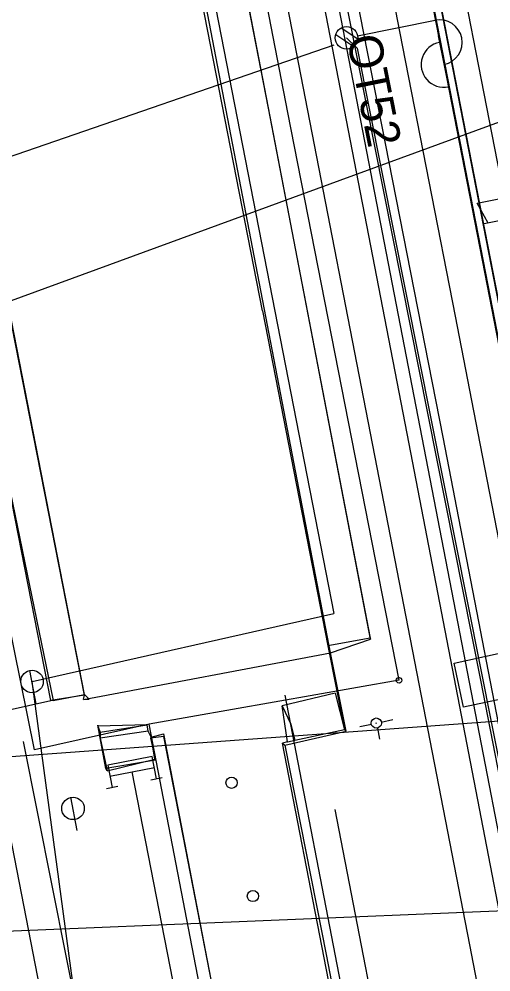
# Model space of a CAD drawing. Extents: x -545736 to -544888, y -1122892 to -1119128.
# Drawn here: x -545210.15 to -545189.26, y -1122030.09 to -1121987.93 of the extents above; entities that cross this region are included whole.
import ezdxf

# ---------------------------------------------------------------- set-up
doc = ezdxf.new("R2010")
doc.units = 0
for name, color, linetype in [('osvětlené plochy-hodnota-obrys', 7, 'Continuous'), ('Podbarveni_Nastupiste', 7, 'Continuous'), ('Podbarveni_Zastreseni_Pozemni', 7, 'Continuous'), ('Vrstva 1', 7, 'Continuous'), ('Vrstva 1 - Koleje', 7, 'Continuous'), ('Vrstva 12', 7, 'Continuous'), ('Vrstva 14_zastreseni a nastupiste', 7, 'Continuous'), ('Vrstva 15', 7, 'Continuous'), ('Vrstva 16_plochy', 7, 'Continuous'), ('Vrstva 17', 7, 'Continuous'), ('Vrstva 23', 7, 'Continuous'), ('Vrstva 25', 7, 'Continuous'), ('Vrstva 26', 7, 'Continuous'), ('Vrstva 33 - prvky sdelzar', 7, 'Continuous'), ('Vrstva 36', 7, 'Continuous'), ('Vrstva 4 - Teren - stezky - prechody - plochy', 7, 'Continuous'), ('Vrstva 41', 7, 'Continuous'), ('Vrstva 42', 7, 'Continuous'), ('Vrstva 43', 7, 'Continuous'), ('Vrstva 44', 7, 'Continuous'), ('Vrstva 51', 7, 'Continuous'), ('Vrstva 63', 7, 'Continuous')]:
    doc.layers.add(name, color=color, linetype=linetype)

msp = doc.modelspace()

# ---------------------------------------------------------------- linework, layer by layer
at = {"layer": 'osvětlené plochy-hodnota-obrys'}
for points in [[(-545132.033, -1122317.745), (-545201.844, -1121957.194), (-545188.779, -1121954.655), (-545199.189, -1121901.389)], [(-545201.844, -1121957.194), (-545207.148, -1121958.23), (-545196.216, -1122014.238)], [(-545179.449, -1122198.287), (-545199.55, -1122091.48), (-545209.58, -1122017.245), (-545196.216, -1122014.238)]]:
    msp.add_lwpolyline(points, dxfattribs=at)
at = {"layer": 'Podbarveni_Nastupiste'}
msp.add_lwpolyline([(-545198.773, -1121951.627), (-545191.691, -1121987.986), (-545182.222, -1122036.609), (-545172.438, -1122086.699), (-545162.999, -1122135.094), (-545153.274, -1122184.937), (-545142.505, -1122240.181), (-545142.306, -1122241.006)], dxfattribs=at)
at = {"layer": 'Podbarveni_Zastreseni_Pozemni'}
msp.add_lwpolyline([(-545197.881, -1121954.495), (-545191.312, -1121988.174), (-545181.806, -1122036.914), (-545172.146, -1122086.438), (-545162.65, -1122135.125), (-545152.971, -1122184.749), (-545143.515, -1122233.227)], dxfattribs=at)
at = {"layer": 'Vrstva 1'}
msp.add_line((-545199.187, -1122051.823), (-545205.146, -1122021.242), dxfattribs=at)
for points in [[(-545171.524, -1122125.069), (-545174.635, -1122109.111), (-545178.563, -1122088.801), (-545181.831, -1122072.035), (-545185.39, -1122053.802), (-545190.2, -1122028.892), (-545193.908, -1122009.819), (-545198.17, -1121987.873), (-545202.45, -1121965.839), (-545203.994, -1121957.813)], [(-545176.125, -1122125.966), (-545177.056, -1122121.203), (-545182.157, -1122094.956), (-545185.515, -1122077.639), (-545188.604, -1122061.78), (-545193.373, -1122037.292), (-545196.156, -1122022.904)]]:
    msp.add_lwpolyline(points, dxfattribs=at)
at = {"layer": 'Vrstva 1 - Koleje'}
msp.add_lwpolyline([(-545199.342, -1121957.379), (-545196.999, -1121969.551), (-545195.085, -1121979.364), (-545193.173, -1121989.165), (-545190.849, -1122001.079), (-545189.753, -1122006.71), (-545187.83, -1122016.562), (-545185.924, -1122026.325), (-545184.013, -1122036.136), (-545182.107, -1122045.899), (-545180.267, -1122055.344), (-545178.296, -1122065.456), (-545176.383, -1122075.263), (-545174.481, -1122085.012)], dxfattribs=at)
at = {"layer": 'Vrstva 12'}
for p, q in [((-545194.605, -1122015.329), (-545194.591, -1122015.372)), ((-545196.48, -1122015.667), (-545196.366, -1122015.979)), ((-545207.256, -1122017.843), (-545208.742, -1122018.083)), ((-545208.65, -1122018.084), (-545207.25, -1122017.815)), ((-545207.25, -1122017.815), (-545207.256, -1122017.843)), ((-545196.154, -1122017.763), (-545198.512, -1122018.313)), ((-545196.154, -1122017.763), (-545195.739, -1122019.386)), ((-545208.65, -1122018.084), (-545208.742, -1122018.083)), ((-545206.57, -1122019.479), (-545204.476, -1122019.159)), ((-545204.438, -1122019.437), (-545206.567, -1122019.748)), ((-545203.763, -1122019.561), (-545203.751, -1122019.67)), ((-545195.668, -1122019.443), (-545195.739, -1122019.386)), ((-545204.299, -1122019.698), (-545204.329, -1122019.745)), ((-545204.143, -1122020.682), (-545204.112, -1122020.72)), ((-545206.251, -1122021.196), (-545206.312, -1122021.094))]:
    msp.add_line(p, q, dxfattribs=at)
for points in [[(-545221.457, -1121952.473), (-545217.829, -1121971.245), (-545212.72, -1121997.564), (-545210.75, -1122007.836), (-545208.65, -1122018.084)], [(-545198.393, -1122020.062), (-545195.668, -1122019.443), (-545196.366, -1122015.979), (-545194.591, -1122015.372), (-545199.107, -1121991.861), (-545202.9, -1121972.236), (-545205.869, -1121956.965), (-545205.949, -1121957.005), (-545202.951, -1121972.246), (-545199.128, -1121991.88), (-545194.605, -1122015.329), (-545196.48, -1122015.667), (-545195.739, -1122019.386), (-545197.952, -1122019.845), (-545198.251, -1122019.924), (-545198.272, -1122019.909), (-545198.489, -1122019.971)], [(-545198.272, -1122019.909), (-545198.512, -1122018.313), (-545198.121, -1122019.129), (-545198.121, -1122019.129), (-545197.952, -1122019.845)], [(-545206.672, -1122019.216), (-545206.57, -1122019.479), (-545206.567, -1122019.748), (-545206.251, -1122021.196), (-545204.143, -1122020.682), (-545204.299, -1122019.698), (-545204.438, -1122019.437), (-545204.476, -1122019.159), (-545206.672, -1122019.216)], [(-545204.299, -1122019.698), (-545203.763, -1122019.561), (-545196.412, -1122057.677), (-545191.231, -1122084.009), (-545184.671, -1122117.574), (-545184.668, -1122117.607), (-545191.105, -1122084.578), (-545196.358, -1122057.64), (-545203.751, -1122019.67), (-545204.329, -1122019.745), (-545204.112, -1122020.72), (-545206.312, -1122021.094), (-545206.672, -1122019.168), (-545206.672, -1122019.216)], [(-545206.558, -1122019.477), (-545206.57, -1122019.479)], [(-545179.655, -1122116.54), (-545186.14, -1122083.56), (-545191.388, -1122056.521), (-545196.648, -1122029.468), (-545198.489, -1122019.971), (-545198.393, -1122020.062), (-545196.548, -1122029.388), (-545191.323, -1122056.562), (-545186.056, -1122083.545), (-545179.629, -1122116.564)]]:
    msp.add_lwpolyline(points, dxfattribs=at)
at = {"layer": 'Vrstva 14_zastreseni a nastupiste'}
for points in [[(-545198.773, -1121951.627), (-545198.793, -1121951.631), (-545197.668, -1121957.434), (-545195.753, -1121967.224), (-545195.374, -1121969.187), (-545193.463, -1121979.015), (-545191.56, -1121988.764), (-545189.639, -1121998.596), (-545187.731, -1122008.385), (-545185.791, -1122018.31), (-545183.91, -1122027.957), (-545182.003, -1122037.734), (-545180.094, -1122047.536), (-545178.189, -1122057.285), (-545176.275, -1122067.11), (-545174.372, -1122076.877), (-545172.469, -1122086.648)], [(-545198.773, -1121951.627), (-545197.637, -1121957.485), (-545195.722, -1121967.275), (-545195.343, -1121969.238), (-545193.432, -1121979.066), (-545191.529, -1121988.815), (-545189.608, -1121998.647), (-545187.7, -1122008.436), (-545185.76, -1122018.361), (-545183.879, -1122028.008), (-545181.972, -1122037.785), (-545180.063, -1122047.587), (-545178.158, -1122057.336), (-545176.244, -1122067.161), (-545174.341, -1122076.928), (-545172.438, -1122086.699)], [(-545143.529, -1122233.23), (-545153.022, -1122184.547), (-545162.697, -1122134.935), (-545172.201, -1122086.2), (-545181.882, -1122036.553), (-545191.387, -1121987.814), (-545197.884, -1121954.495)], [(-545197.881, -1121954.495), (-545191.312, -1121988.174), (-545181.806, -1122036.914), (-545172.146, -1122086.438), (-545162.65, -1122135.125), (-545152.971, -1122184.749), (-545143.515, -1122233.229)]]:
    msp.add_lwpolyline(points, dxfattribs=at)
at = {"layer": 'Vrstva 15'}
for p, q in [((-545206.128, -1122021.433), (-545204.164, -1122021.051)), ((-545204.314, -1122021.589), (-545203.823, -1122021.494)), ((-545206.277, -1122021.972), (-545205.787, -1122021.876))]:
    msp.add_line(p, q, dxfattribs=at)
msp.add_lwpolyline([(-545204.069, -1122021.542), (-545204.26, -1122020.56), (-545206.223, -1122020.942), (-545206.032, -1122021.924)], dxfattribs=at)
at = {"layer": 'Vrstva 16_plochy'}
msp.add_lwpolyline([(-545172.438, -1122086.699), (-545174.341, -1122076.928), (-545176.244, -1122067.161), (-545178.158, -1122057.336), (-545180.063, -1122047.587), (-545181.972, -1122037.785), (-545183.879, -1122028.008), (-545185.76, -1122018.361), (-545187.7, -1122008.436), (-545189.608, -1121998.647), (-545191.529, -1121988.815), (-545193.432, -1121979.066), (-545195.343, -1121969.238), (-545195.722, -1121967.275), (-545197.637, -1121957.485), (-545198.773, -1121951.627)], dxfattribs=at)
at = {"layer": 'Vrstva 17'}
msp.add_lwpolyline([(-545209.978, -1122019.893), (-545196.019, -1122089.973), (-545200.414, -1122090.871), (-545193.769, -1122123.214)], dxfattribs=at)
at = {"layer": 'Vrstva 23'}
for p, q in [((-545196.366, -1122015.979), (-545209.259, -1121948.92)), ((-545207.256, -1122017.843), (-545220.407, -1121951.064)), ((-545207.25, -1122017.815), (-545220.159, -1121952.227)), ((-545199.383, -1122000.837), (-545196.48, -1122015.667)), ((-545207.294, -1122018.041), (-545207.256, -1122017.843)), ((-545207.053, -1122018.03), (-545207.25, -1122017.815)), ((-545179.479, -1122115.355), (-545198.377, -1122017.846)), ((-545207.294, -1122018.041), (-545207.053, -1122018.03)), ((-545185.499, -1122116.633), (-545204.397, -1122019.124))]:
    msp.add_line(p, q, dxfattribs=at)
for points in [[(-545199.383, -1122000.837), (-545202.829, -1121983.168), (-545208.015, -1121956.626), (-545209.317, -1121949.263), (-545209.259, -1121948.92), (-545210.612, -1121942.089), (-545208.554, -1121941.671), (-545213.053, -1121919.523), (-545225.888, -1121922.128)], [(-545209.473, -1122020.261), (-545214.34, -1121996.237), (-545218.36, -1121975.647), (-545223.024, -1121951.493), (-545220.12, -1121951.013)], [(-545193.331, -1122017.189), (-545198.252, -1121992.071), (-545203.434, -1121965.339)], [(-545207.294, -1122018.041), (-545196.366, -1122015.979)], [(-545193.331, -1122017.189), (-545204.397, -1122019.124), (-545209.473, -1122020.261)]]:
    msp.add_lwpolyline(points, dxfattribs=at)
msp.add_circle((-545193.331, -1122017.189), 0.125, dxfattribs=at)
at = {"layer": 'Vrstva 25'}
for p, q in [((-545195.164, -1121988.669), (-545191.731, -1121987.986)), ((-545195.89, -1121988.327), (-545195.159, -1121988.815)), ((-545196.129, -1121988.618), (-545195.333, -1121989.15)), ((-545191.594, -1121988.673), (-545191.087, -1121991.223))]:
    msp.add_line(p, q, dxfattribs=at)
msp.add_circle((-545195.654, -1121988.767), 0.5, dxfattribs=at)
msp.add_circle((-545195.654, -1121988.767), 0.5, dxfattribs=at)
for centre, start, end in [((-545191.536, -1121988.967), 281.2532, 101.2532), ((-545191.353, -1121989.95), 100.5506, 281.9557)]:
    msp.add_arc(centre, 1, start, end, dxfattribs=at)
at = {"layer": 'Vrstva 26'}
msp.add_lwpolyline([(-545195.654, -1121988.767), (-545195.18, -1121989.223), (-545187.569, -1122027.475), (-545180.363, -1122064.26), (-545172.911, -1122102.258), (-545175.755, -1122102.852), (-545177.675, -1122103.151), (-545178.018, -1122103.363), (-545177.842, -1122104.444), (-545175.244, -1122116.91), (-545174.048, -1122121.099), (-545173.902, -1122123.794), (-545172.196, -1122133.711), (-545171.232, -1122138.713), (-545170.128, -1122141.107), (-545170.035, -1122141.928), (-545170.255, -1122143.199), (-545168.934, -1122149.868), (-545168.557, -1122151.414), (-545168.549, -1122152.817), (-545167.193, -1122160.014), (-545166.201, -1122166.567)], dxfattribs=at)
at = {"layer": 'Vrstva 33 - prvky sdelzar'}
msp.add_line((-545187.81, -1121996.65), (-545189.569, -1121996.994), dxfattribs=at)
msp.add_lwpolyline([(-545189.38, -1121996.957), (-545189.879, -1121996.076), (-545188.622, -1121995.831), (-545188.752, -1121996.834)], dxfattribs=at)
at = {"layer": 'Vrstva 36'}
for centre in [(-545200.745, -1122021.718), (-545199.8, -1122026.732)]:
    msp.add_circle(centre, 0.25, dxfattribs=at)
at = {"layer": 'Vrstva 4 - Teren - stezky - prechody - plochy'}
for points in [[(-545202.565, -1121956.903), (-545201.056, -1121956.644), (-545199.526, -1121965.043), (-545191.386, -1122006.433), (-545183.698, -1122046.146), (-545176.813, -1122081.324), (-545170.865, -1122111.978), (-545164.201, -1122145.846), (-545158.369, -1122175.606), (-545150.392, -1122216.501), (-545142.671, -1122256.585), (-545144.174, -1122256.905)], [(-545202.565, -1121956.903), (-545200.961, -1121965.123), (-545192.99, -1122006.271), (-545185.214, -1122046.565), (-545178.591, -1122080.816), (-545172.231, -1122113.527), (-545166.05, -1122145.218), (-545159.636, -1122177.662), (-545152.008, -1122216.815), (-545144.174, -1122256.905)], [(-545182.003, -1122037.734), (-545183.91, -1122027.957), (-545185.791, -1122018.31), (-545187.731, -1122008.385), (-545189.639, -1121998.596), (-545191.56, -1121988.764), (-545193.463, -1121979.015)]]:
    msp.add_lwpolyline(points, dxfattribs=at)
at = {"layer": 'Vrstva 41'}
for p, q in [((-545195.071, -1122019.232), (-545194.557, -1122019.126)), ((-545194.361, -1122019.085), (-545194.313, -1122019.075)), ((-545194.117, -1122019.034), (-545193.603, -1122018.928)), ((-545194.291, -1122019.3), (-545194.19, -1122019.79))]:
    msp.add_line(p, q, dxfattribs=at)
msp.add_lwpolyline([(-545190.895, -1122016.424), (-545188.939, -1122016.008), (-545188.523, -1122017.964), (-545190.479, -1122018.38), (-545190.895, -1122016.424)], dxfattribs=at)
msp.add_circle((-545194.337, -1122019.08), 0.225, dxfattribs=at)
at = {"layer": 'Vrstva 42'}
msp.add_lwpolyline([(-545200.311, -1121937.722), (-545199.74, -1121939.864), (-545198.486, -1121946.055), (-545198.782, -1121952.405), (-545201.965, -1121955.297), (-545200.981, -1121959.998), (-545197.52, -1121977.94), (-545189.718, -1122017.188), (-545181.934, -1122057.193)], dxfattribs=at)
at = {"layer": 'Vrstva 43'}
for p, q in [((-545209.39, -1122018.227), (-545209.674, -1122016.756)), ((-545207.574, -1122023.837), (-545207.86, -1122022.366))]:
    msp.add_line(p, q, dxfattribs=at)
for centre in [(-545209.58, -1122017.245), (-545207.765, -1122022.855)]:
    msp.add_circle(centre, 0.498, dxfattribs=at)
at = {"layer": 'Vrstva 44'}
msp.add_lwpolyline([(-545180.662, -1122034.333), (-545184.014, -1122019.078), (-545187.459, -1122002.038), (-545190.967, -1121984.029), (-545191.024, -1121983.688), (-545190.997, -1121983.256), (-545190.532, -1121983.18), (-545188.483, -1121982.815), (-545188.273, -1121982.75), (-545188.289, -1121982.487), (-545190.918, -1121967.576), (-545192.659, -1121959.264), (-545194.003, -1121953.627), (-545194.032, -1121953.413), (-545194.056, -1121953.159), (-545196.062, -1121942.809), (-545198.906, -1121928.142)], dxfattribs=at)
at = {"layer": 'Vrstva 51'}
for points in [[(-545211.598, -1122018.709), (-545208.742, -1122018.083), (-545210.751, -1122007.845), (-545213.194, -1122008.281), (-545215.183, -1121998.047), (-545212.784, -1121997.542), (-545214.798, -1121986.713), (-545218.624, -1121980.315), (-545218.98, -1121978.367), (-545217.359, -1121974.247), (-545219.31, -1121963.742), (-545221.752, -1121951.253), (-545223.058, -1121944.388), (-545225.381, -1121941.61), (-545225.816, -1121939.244), (-545222.78, -1121938.7)], [(-545206.031, -1122092.762), (-545204.034, -1122092.23), (-545201.056, -1122090.338), (-545199.23, -1122087.125), (-545198.864, -1122084.006), (-545199.944, -1122078.233), (-545205.433, -1122050.352), (-545211.598, -1122018.709)]]:
    msp.add_lwpolyline(points, dxfattribs=at)
at = {"layer": 'Vrstva 63'}
for p, q in [((-545166.811, -1121984.402), (-545257.147, -1122017.472)), ((-545196.217, -1121989.085), (-545258.497, -1122010.578)), ((-545162.956, -1122017.089), (-545255.888, -1122023.906)), ((-545188.294, -1122027.379), (-545254.674, -1122030.11))]:
    msp.add_line(p, q, dxfattribs=at)

# ---------------------------------------------------------------- texts
at = {"layer": 'Vrstva 25'}
msp.add_text('OT52', height=1.5, rotation=281.2532, dxfattribs=at).set_placement((-545195.654, -1121988.767))

doc.saveas('drawing.dxf')
